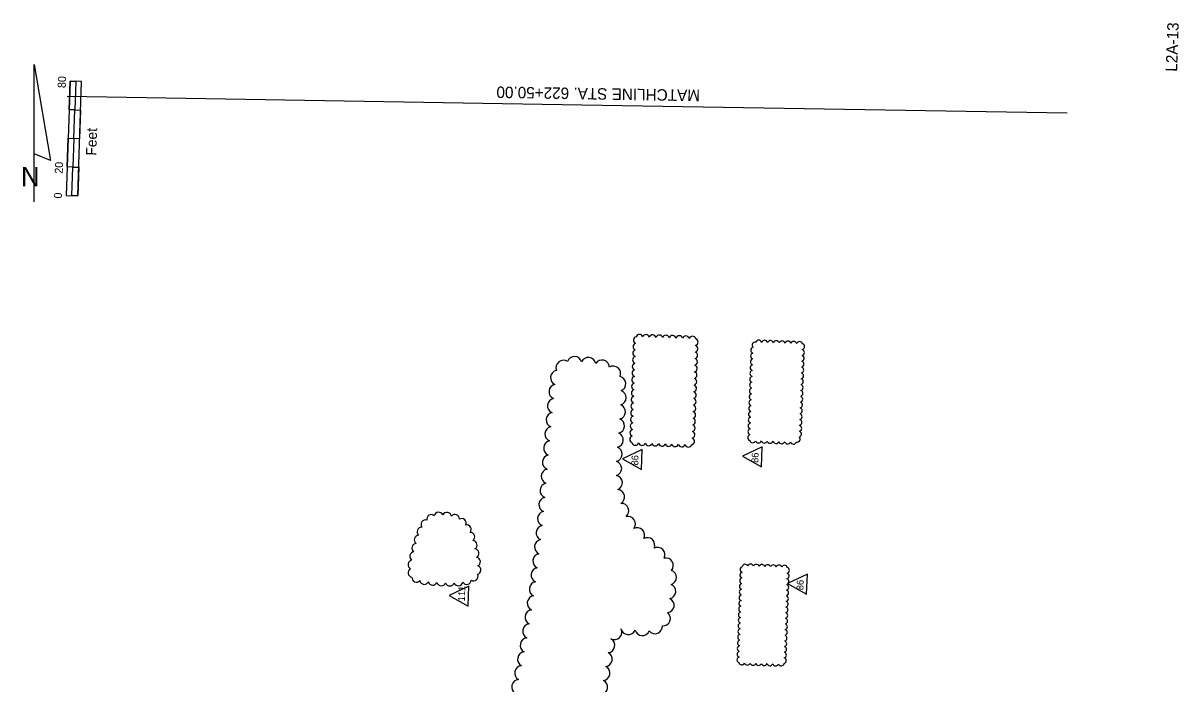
# Model space of a CAD drawing. Extents: x 928669 to 929521, y 636891 to 638153.
# Drawn here: x 928712 to 929521, y 637690 to 638153 of the extents above; entities that cross this region are included whole.
import ezdxf

# ---------------------------------------------------------------- set-up
doc = ezdxf.new("R2010")
doc.units = 0
for name, color, linetype in [('Cloud_dp', 7, 'Continuous'), ('MatchLines_dp', 7, 'Continuous'), ('NorthArw_dp', 7, 'Continuous'), ('Scale_dp', 7, 'Continuous'), ('TextShtNo', 7, 'Continuous')]:
    doc.layers.add(name, color=color, linetype=linetype)

msp = doc.modelspace()

# ---------------------------------------------------------------- linework, layer by layer
at = {"layer": 'Cloud_dp'}
for points in [[(929131.74, 637847.81), (929145.05, 637840.3), (929145.54, 637854.37)], [(929215.77, 637849.63), (929229.08, 637842.12), (929229.57, 637856.19)], [(929247.3, 637760.56), (929260.6, 637753.05), (929261.1, 637767.12)], [(929010.47, 637752.24), (929023.78, 637744.73), (929024.28, 637758.81)]]:
    msp.add_lwpolyline(points, close=True, dxfattribs=at)
for centre, radius, start, end in [((929141.85, 637930.91), 2.43, 102.2454, 247.2454), ((929143.62, 637932.47), 2.43, 15.49782, 160.49782), ((929148.26, 637932.31), 2.43, 15.49782, 160.49782), ((929152.89, 637932.15), 2.43, 15.49782, 160.49782), ((929157.53, 637931.99), 2.43, 15.49782, 160.49782), ((929162.16, 637931.83), 2.43, 15.49782, 160.49782), ((929166.8, 637931.66), 2.43, 15.49782, 160.49782), ((929171.44, 637931.5), 2.43, 15.49782, 160.49782), ((929176.07, 637931.34), 2.43, 15.49782, 160.49782), ((929180.71, 637931.18), 2.43, 15.49782, 160.49782), ((929141.4, 637921.68), 2.43, 105.49782, 250.49782), ((929141.56, 637926.32), 2.43, 105.49782, 250.49782), ((929182.08, 637924.9), 2.43, 285.49782, 70.49782), ((929182.24, 637929.54), 2.43, 285.49782, 70.49782), ((929223.65, 637923.84), 2.14, 105.49782, 250.49782), ((929224.64, 637927.35), 2.14, 77.99311, 222.99311), ((929227.1, 637928.73), 2.14, 15.49782, 160.49782), ((929231.18, 637928.59), 2.14, 15.49782, 160.49782), ((929235.25, 637928.44), 2.14, 15.49782, 160.49782), ((929239.33, 637928.3), 2.14, 15.49782, 160.49782), ((929243.4, 637928.16), 2.14, 15.49782, 160.49782), ((929247.48, 637928.02), 2.14, 15.49782, 160.49782), ((929251.56, 637927.87), 2.14, 15.49782, 160.49782), ((929255.63, 637927.73), 2.14, 15.49782, 160.49782), ((929256.84, 637922.21), 2.14, 285.49782, 70.49782), ((929256.98, 637926.29), 2.14, 285.49782, 70.49782), ((929090.43, 637911.59), 5.19, 56.41355, 201.41355), ((929098.21, 637914.21), 5.2, 15.84807, 160.84807), ((929107.95, 637913.52), 5.2, 11.04906, 156.04906), ((929117.44, 637911.73), 5.2, 2.63386, 147.63386), ((929141.23, 637917.05), 2.43, 105.49782, 250.49782), ((929181.75, 637915.63), 2.43, 285.49782, 70.49782), ((929181.91, 637920.26), 2.43, 285.49782, 70.49782), ((929223.36, 637915.68), 2.14, 105.49782, 250.49782), ((929223.51, 637919.76), 2.14, 105.49782, 250.49782), ((929256.55, 637914.06), 2.14, 285.49782, 70.49782), ((929256.69, 637918.13), 2.14, 285.49782, 70.49782), ((929086.62, 637904.6), 5.2, 101.46649, 246.46649), ((929125.31, 637907.52), 5.19, 335.97351, 120.97351), ((929140.91, 637907.78), 2.43, 105.49782, 250.49782), ((929141.07, 637912.41), 2.43, 105.49782, 250.49782), ((929181.43, 637906.36), 2.43, 285.49782, 70.49782), ((929181.59, 637910.99), 2.43, 285.49782, 70.49782), ((929223.08, 637907.53), 2.14, 105.49782, 250.49782), ((929223.22, 637911.61), 2.14, 105.49782, 250.49782), ((929256.27, 637905.91), 2.14, 285.49782, 70.49782), ((929256.41, 637909.98), 2.14, 285.49782, 70.49782), ((929085.54, 637894.74), 5.2, 100.97125, 245.97125), ((929128.89, 637900.34), 5.2, 292.0696, 77.0696), ((929140.59, 637898.51), 2.43, 105.49782, 250.49782), ((929140.75, 637903.14), 2.43, 105.49782, 250.49782), ((929181.27, 637901.72), 2.43, 285.49782, 70.49782), ((929222.79, 637899.38), 2.14, 105.49782, 250.49782), ((929222.94, 637903.45), 2.14, 105.49782, 250.49782), ((929255.98, 637897.75), 2.14, 285.49782, 70.49782), ((929256.12, 637901.83), 2.14, 285.49782, 70.49782), ((929129.13, 637890.62), 5.2, 285.7825, 70.7825), ((929140.26, 637889.24), 2.43, 105.49782, 250.49782), ((929140.42, 637893.87), 2.43, 105.49782, 250.49782), ((929180.94, 637892.45), 2.43, 285.49782, 70.49782), ((929181.1, 637897.09), 2.43, 285.49782, 70.49782), ((929222.51, 637891.23), 2.14, 105.49782, 250.49782), ((929222.65, 637895.3), 2.14, 105.49782, 250.49782), ((929255.7, 637889.6), 2.14, 285.49782, 70.49782), ((929255.84, 637893.68), 2.14, 285.49782, 70.49782), ((929084.5, 637884.91), 5.2, 101.95868, 246.95868), ((929128.68, 637880.77), 5.2, 283.99541, 68.99541), ((929140.1, 637884.6), 2.43, 105.49782, 250.49782), ((929180.62, 637883.18), 2.43, 285.49782, 70.49782), ((929180.78, 637887.82), 2.43, 285.49782, 70.49782), ((929222.22, 637883.07), 2.14, 105.49782, 250.49782), ((929222.37, 637887.15), 2.14, 105.49782, 250.49782), ((929255.41, 637881.45), 2.14, 285.49782, 70.49782), ((929255.55, 637885.52), 2.14, 285.49782, 70.49782), ((929083.57, 637875.05), 5.2, 102.29688, 247.29688), ((929127.99, 637870.91), 5.2, 283.0349, 68.0349), ((929139.78, 637875.33), 2.43, 105.49782, 250.49782), ((929139.94, 637879.97), 2.43, 105.49782, 250.49782), ((929180.29, 637873.91), 2.43, 285.49782, 70.49782), ((929180.45, 637878.55), 2.43, 285.49782, 70.49782), ((929221.94, 637874.92), 2.14, 105.49782, 250.49782), ((929222.08, 637879), 2.14, 105.49782, 250.49782), ((929255.27, 637877.37), 2.14, 285.49782, 70.49782), ((929082.69, 637865.18), 5.2, 102.47183, 247.47183), ((929139.45, 637866.06), 2.43, 105.49782, 250.49782), ((929139.61, 637870.69), 2.43, 105.49782, 250.49782), ((929180.13, 637869.28), 2.43, 285.49782, 70.49782), ((929221.65, 637866.77), 2.14, 105.49782, 250.49782), ((929221.8, 637870.84), 2.14, 105.49782, 250.49782), ((929254.98, 637869.22), 2.14, 285.49782, 70.49782), ((929255.13, 637873.29), 2.14, 285.49782, 70.49782), ((929081.83, 637855.31), 5.2, 102.5836, 247.5836), ((929127.17, 637861.05), 5.2, 282.41116, 67.41116), ((929139.29, 637861.42), 2.43, 105.49782, 250.49782), ((929179.68, 637860.05), 2.43, 282.2454, 67.2454), ((929179.97, 637864.64), 2.43, 285.49782, 70.49782), ((929221.51, 637862.69), 2.14, 105.49782, 250.49782), ((929222.86, 637861.25), 2.14, 195.49782, 340.49782), ((929226.93, 637861.1), 2.14, 195.49782, 340.49782), ((929231.01, 637860.96), 2.14, 195.49782, 340.49782), ((929235.09, 637860.82), 2.14, 195.49782, 340.49782), ((929239.16, 637860.68), 2.14, 195.49782, 340.49782), ((929243.24, 637860.53), 2.14, 195.49782, 340.49782), ((929247.31, 637860.39), 2.14, 195.49782, 340.49782), ((929251.39, 637860.25), 2.14, 195.49782, 340.49782), ((929253.85, 637861.62), 2.14, 257.99311, 42.99311), ((929254.84, 637865.14), 2.14, 285.49782, 70.49782), ((929126.37, 637851.14), 5.2, 283.37346, 68.37346), ((929140.82, 637859.78), 2.43, 195.49782, 340.49782), ((929145.46, 637859.62), 2.43, 195.49782, 340.49782), ((929150.09, 637859.46), 2.43, 195.49782, 340.49782), ((929154.73, 637859.3), 2.43, 195.49782, 340.49782), ((929159.36, 637859.13), 2.43, 195.49782, 340.49782), ((929164, 637858.97), 2.43, 195.49782, 340.49782), ((929168.63, 637858.81), 2.43, 195.49782, 340.49782), ((929173.27, 637858.65), 2.43, 195.49782, 340.49782), ((929177.9, 637858.49), 2.43, 195.49782, 340.49782), ((929080.99, 637845.44), 5.2, 102.66298, 247.66298), ((929126.01, 637841.13), 5.2, 287.51688, 72.51688), ((929080.16, 637835.57), 5.2, 102.72312, 247.72312), ((929126.49, 637831.1), 5.2, 292.89, 77.89), ((929079.33, 637825.69), 5.2, 102.68687, 247.68687), ((929078.47, 637815.81), 5.2, 102.33577, 247.33577), ((929128.04, 637821.14), 5.2, 299.87832, 84.87832), ((929077.54, 637805.93), 5.2, 101.93734, 246.93734), ((929130.99, 637811.45), 5.2, 308.96359, 93.96359), ((928994, 637801.89), 3.16, 73.61222, 218.61222), ((928997.97, 637805.63), 3.16, 47.9357, 192.9357), ((929003.18, 637807.32), 3.16, 23.01584, 168.01584), ((929008.96, 637807.24), 3.16, 10.39129, 155.39129), ((929014.51, 637805.81), 3.16, 355.83562, 140.83562), ((929019.25, 637802.86), 3.16, 335.22185, 120.22185), ((929135.63, 637802.4), 5.2, 320.34498, 105.34498), ((928991.24, 637796.78), 3.16, 84.72044, 229.72044), ((929022.83, 637798.46), 3.16, 318.05042, 103.05042), ((929025.26, 637793.19), 3.16, 306.37477, 91.37477), ((929076.54, 637796.06), 5.2, 101.51635, 246.51635), ((929142.01, 637794.46), 5.2, 332.26257, 117.26257), ((928987.6, 637785.45), 3.16, 93.05184, 238.05184), ((928989.22, 637791.21), 3.16, 90.44319, 235.44319), ((929026.93, 637787.49), 3.16, 301.37769, 86.37769), ((929075.47, 637786.19), 5.2, 101.07066, 246.07066), ((929149.15, 637787.51), 5.2, 334.27019, 119.27019), ((928986.1, 637779.62), 3.16, 93.11638, 238.11638), ((929028.24, 637781.65), 3.16, 298.87483, 83.87483), ((929029.22, 637775.78), 3.16, 295.01521, 80.01521), ((929074.32, 637776.34), 5.2, 100.59786, 245.59786), ((929156.28, 637780.68), 5.2, 333.1711, 118.1711), ((929162.11, 637773.28), 5.2, 318.19524, 103.19524), ((928984.95, 637773.82), 3.16, 99.50187, 244.50187), ((928984.99, 637768.14), 3.16, 116.22865, 261.22865), ((929029.55, 637769.92), 3.16, 286.48352, 71.48352), ((929073.08, 637766.49), 5.2, 100.09518, 245.09518), ((929216.09, 637770.42), 2.07, 105.49782, 250.49782), ((929217.56, 637771.99), 2.07, 22.9065, 167.9065), ((929221.42, 637772.1), 2.07, 15.49782, 160.49782), ((929225.37, 637771.96), 2.07, 15.49782, 160.49782), ((929229.32, 637771.83), 2.07, 15.49782, 160.49782), ((929233.27, 637771.69), 2.07, 15.49782, 160.49782), ((929237.22, 637771.55), 2.07, 15.49782, 160.49782), ((929241.17, 637771.41), 2.07, 15.49782, 160.49782), ((929245.12, 637771.27), 2.07, 15.49782, 160.49782), ((929246.43, 637769.87), 2.07, 285.49782, 70.49782), ((928987.65, 637764.69), 3.16, 173.96501, 318.96501), ((928993.14, 637763.17), 3.16, 190.07616, 335.07616), ((929022.79, 637763.13), 3.16, 210.77181, 355.77181), ((929027.56, 637765.6), 3.16, 239.01874, 24.01874), ((929164.34, 637764.88), 5.2, 286.64585, 71.64585), ((929215.81, 637762.52), 2.07, 105.49782, 250.49782), ((929215.95, 637766.47), 2.07, 105.49782, 250.49782), ((929246.15, 637761.97), 2.07, 285.49782, 70.49782), ((929246.29, 637765.92), 2.07, 285.49782, 70.49782), ((928999.08, 637762.56), 3.16, 193.28423, 338.28423), ((929005.07, 637762.2), 3.16, 194.91907, 339.91907), ((929011.06, 637762.05), 3.16, 197.10598, 342.10598), ((929017, 637762.24), 3.16, 201.65335, 346.65335), ((929071.76, 637756.66), 5.2, 99.55946, 244.55946), ((929163.86, 637755.1), 5.2, 282.66053, 67.66053), ((929215.53, 637754.62), 2.07, 105.49782, 250.49782), ((929215.67, 637758.57), 2.07, 105.49782, 250.49782), ((929245.87, 637754.07), 2.07, 285.49782, 70.49782), ((929246.01, 637758.02), 2.07, 285.49782, 70.49782), ((929070.34, 637746.83), 5.2, 98.98708, 243.98708), ((929162.68, 637745.38), 5.2, 278.50366, 63.50366), ((929215.26, 637746.72), 2.07, 105.49782, 250.49782), ((929215.39, 637750.67), 2.07, 105.49782, 250.49782), ((929245.6, 637746.17), 2.07, 285.49782, 70.49782), ((929245.74, 637750.12), 2.07, 285.49782, 70.49782), ((929068.81, 637737.02), 5.2, 98.37384, 243.37384), ((929160.13, 637736.23), 5.2, 265.40908, 50.40908), ((929214.98, 637738.82), 2.07, 105.49782, 250.49782), ((929215.12, 637742.77), 2.07, 105.49782, 250.49782), ((929245.32, 637738.27), 2.07, 285.49782, 70.49782), ((929245.46, 637742.22), 2.07, 285.49782, 70.49782), ((929067.18, 637727.23), 5.2, 97.71568, 242.71568), ((929154.53, 637730.72), 5.2, 218.71481, 3.71481), ((929214.7, 637730.92), 2.07, 105.49782, 250.49782), ((929214.84, 637734.87), 2.07, 105.49782, 250.49782), ((929245.05, 637730.37), 2.07, 285.49782, 70.49782), ((929245.18, 637734.32), 2.07, 285.49782, 70.49782), ((929065.44, 637717.45), 5.2, 97.03259, 242.03259), ((929121.19, 637717.44), 5.2, 276.02498, 61.02498), ((929126.11, 637726.6), 5.19, 242.48667, 27.48667), ((929135.8, 637730.09), 5.2, 192.20689, 337.20689), ((929145.63, 637729.33), 5.2, 193.96731, 338.96731), ((929214.43, 637723.02), 2.07, 105.49782, 250.49782), ((929214.57, 637726.97), 2.07, 105.49782, 250.49782), ((929244.77, 637722.47), 2.07, 285.49782, 70.49782), ((929244.91, 637726.42), 2.07, 285.49782, 70.49782), ((929214.15, 637715.12), 2.07, 105.49782, 250.49782), ((929214.29, 637719.07), 2.07, 105.49782, 250.49782), ((929244.49, 637714.56), 2.07, 285.49782, 70.49782), ((929244.63, 637718.51), 2.07, 285.49782, 70.49782), ((929063.57, 637707.7), 5.2, 96.30957, 241.30957), ((929119.36, 637707.66), 5.2, 277.75376, 62.75376), ((929213.88, 637707.21), 2.07, 105.49782, 250.49782), ((929214.01, 637711.16), 2.07, 105.49782, 250.49782), ((929244.22, 637706.66), 2.07, 285.49782, 70.49782), ((929244.36, 637710.61), 2.07, 285.49782, 70.49782), ((929061.58, 637697.97), 5.2, 95.52893, 240.52893), ((929117.73, 637697.86), 5.2, 278.37554, 63.37554), ((929215.18, 637705.81), 2.07, 195.49782, 340.49782), ((929219.13, 637705.68), 2.07, 195.49782, 340.49782), ((929223.08, 637705.54), 2.07, 195.49782, 340.49782), ((929227.03, 637705.4), 2.07, 195.49782, 340.49782), ((929230.98, 637705.26), 2.07, 195.49782, 340.49782), ((929234.93, 637705.12), 2.07, 195.49782, 340.49782), ((929238.88, 637704.99), 2.07, 195.49782, 340.49782), ((929242.75, 637705.1), 2.07, 202.9065, 347.9065), ((929059.45, 637688.27), 5.2, 94.68307, 239.68307), ((929116.19, 637688.07), 5.2, 278.7266, 63.7266)]:
    msp.add_arc(centre, radius, start, end, dxfattribs=at)
at = {"layer": 'MatchLines_dp'}
msp.add_lwpolyline([(929442.86, 638089.68), (929103.36, 638095.32), (928743.41, 638101.3)], dxfattribs=at)
at = {"layer": 'NorthArw_dp'}
msp.add_line((928720.15, 638027.69), (928720.15, 638123.69), dxfattribs=at)
msp.add_lwpolyline([(928720.15, 638061.29), (928720.15, 638123.69), (928731.67, 638056.49)], close=True, dxfattribs=at)
at = {"layer": 'Scale_dp'}
for p, q in [((928745.46, 638112.01), (928742.66, 638032.06)), ((928753.45, 638111.73), (928745.46, 638112.01)), ((928750.66, 638031.78), (928753.45, 638111.73)), ((928742.66, 638032.06), (928750.66, 638031.78))]:
    msp.add_line(p, q, dxfattribs=at)
for points in [[(928748.76, 638091.88), (928744.76, 638092.02), (928745.46, 638112.01), (928749.45, 638111.87)], [(928752.05, 638071.75), (928748.06, 638071.89), (928748.76, 638091.88), (928752.75, 638091.74)], [(928747.36, 638051.91), (928743.36, 638052.05), (928744.06, 638072.03), (928748.06, 638071.89)], [(928750.66, 638031.78), (928746.66, 638031.92), (928747.36, 638051.91), (928751.36, 638051.77)]]:
    msp.add_lwpolyline(points, close=True, dxfattribs=at)

# ---------------------------------------------------------------- texts
at = {"layer": 'Cloud_dp'}
for s, p in [('86', (929226.77, 637844.98)), ('86', (929142.74, 637843.16)), ('86', (929258.29, 637755.91)), ('111', (929021.49, 637748.22))]:
    msp.add_text(s, height=4.8, rotation=87.99782, dxfattribs=at).set_placement(p)
at = {"layer": 'MatchLines_dp'}
msp.add_text('MATCHLINE STA. 622+50.00', height=8, rotation=179.04782, dxfattribs=at).set_placement((929186.06, 638105.95))
at = {"layer": 'NorthArw_dp'}
msp.add_text('N', height=13.43, dxfattribs=at).set_placement((928711.03, 638038.56))
at = {"layer": 'Scale_dp'}
for s, height, p in [('80', 5.6, (928742.28, 638107.13)), ('Feet', 7.2, (928763.65, 638059.88)), ('20', 5.6, (928740.19, 638047.19)), ('0', 5.6, (928739.58, 638029.83))]:
    msp.add_text(s, height=height, rotation=87.99782, dxfattribs=at).set_placement(p)
at = {"layer": 'TextShtNo'}
msp.add_text('L2A-13', height=8, rotation=87.99782, dxfattribs=at).set_placement((929519.72, 638118.51))

doc.saveas('drawing.dxf')
